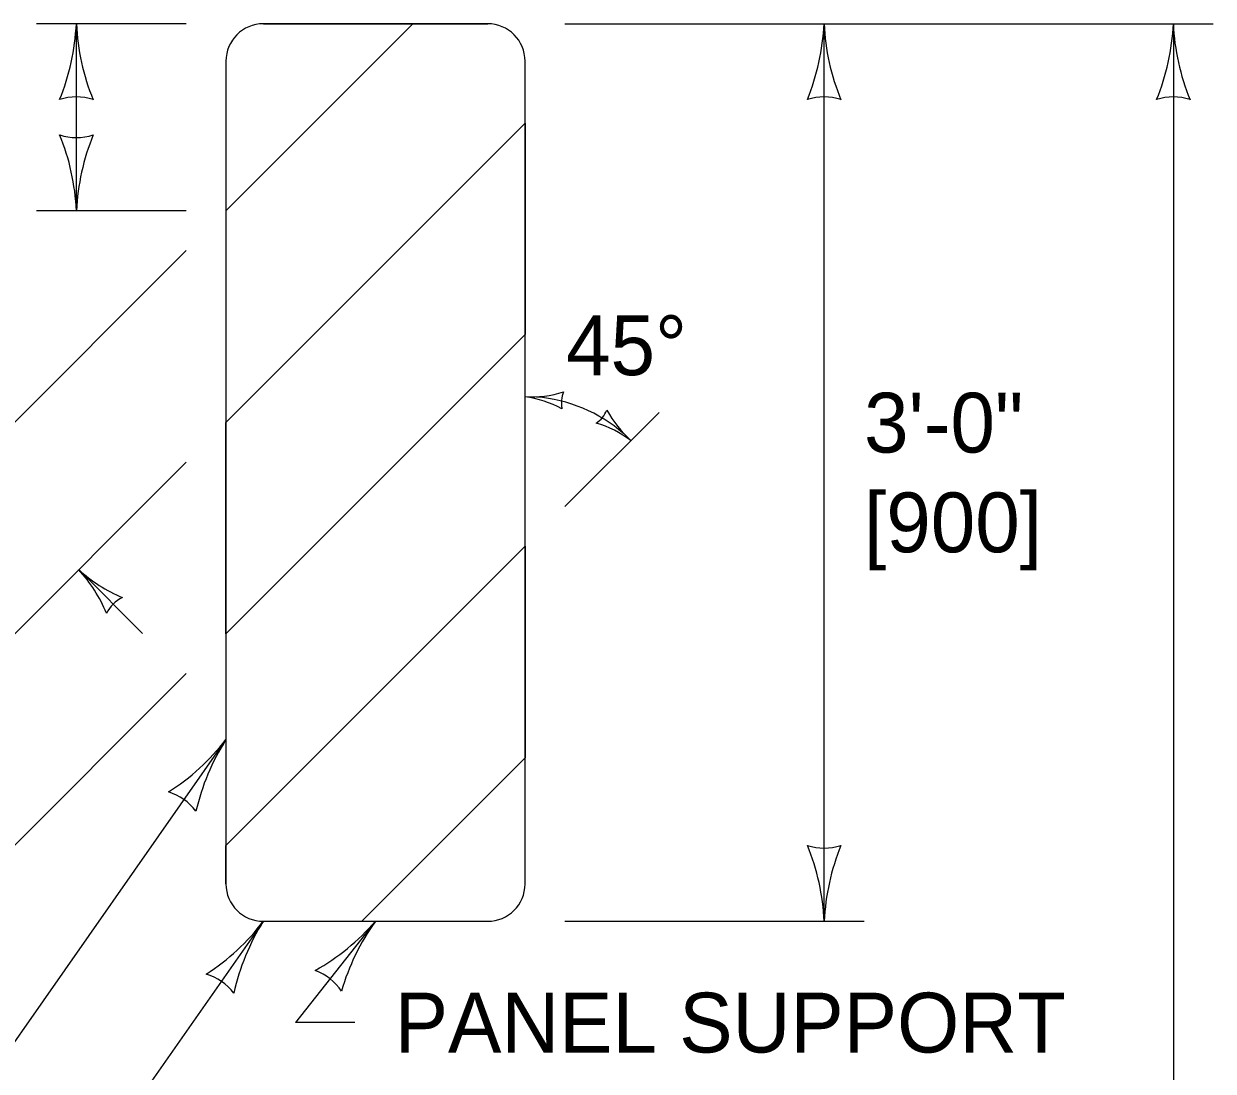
# Model space of a CAD drawing. Extents: x 49991.4 to 50024.6, y 49987.6 to 50011.4.
# Drawn here: x 50012.267 to 50013.46, y 49996.958 to 49998.009 of the extents above; entities that cross this region are included whole.
import ezdxf

# ---------------------------------------------------------------- set-up
doc = ezdxf.new("R2010")
doc.units = 0
doc.layers.add('Level 2', color=7, linetype='Continuous')
doc.layers.add('Level 3', color=7, linetype='Continuous')

msp = doc.modelspace()

# ---------------------------------------------------------------- linework, layer by layer
at = {"layer": 'Level 2'}
for p, q in [((50012.6573, 49998.0086), (50012.4698, 49997.8211)), ((50012.7323, 49998.0086), (50012.6573, 49998.0086)), ((50012.4698, 49997.6089), (50012.7698, 49997.9089)), ((50012.7698, 49997.9089), (50012.7698, 49997.6969)), ((50012.7698, 49997.6969), (50012.4698, 49997.3969)), ((50012.4698, 49997.3969), (50012.4698, 49997.6089)), ((50012.4698, 49997.1847), (50012.7698, 49997.4847)), ((50012.7698, 49997.4847), (50012.7698, 49997.2725)), ((50012.7698, 49997.2725), (50012.6059, 49997.1086)), ((50012.4698, 49997.1461), (50012.4698, 49997.1847))]:
    msp.add_line(p, q, dxfattribs=at)
for points in [[(50012.5073, 49998.0086), (50012.7323, 49998.0086)], [(50012.7323, 49998.0086), (50012.5073, 49998.0086)], [(50012.4698, 49997.9711), (50012.4698, 49997.1461)], [(50012.4698, 49997.9711), (50012.4698, 49997.1461)], [(50012.7698, 49997.1461), (50012.7698, 49997.9711)], [(50012.5073, 49997.1086), (50012.7323, 49997.1086)], [(50012.5073, 49997.1086), (50012.7323, 49997.1086)]]:
    msp.add_lwpolyline(points, dxfattribs=at)
for centre, start, end in [((50012.5073, 49997.9711), 90, 180), ((50012.5073, 49997.9711), 90, 180), ((50012.7323, 49997.9711), 0, 90), ((50012.5073, 49997.1461), 180, 270), ((50012.5073, 49997.1461), 180, 270), ((50012.7323, 49997.1461), 270, 0)]:
    msp.add_arc(centre, 0.0375, start, end, dxfattribs=at)
at = {"layer": 'Level 3'}
for p, q in [((50012.4298, 49998.0086), (50012.2798, 49998.0086)), ((50012.3198, 49997.8211), (50012.3198, 49998.0086)), ((50012.8098, 49998.0086), (50013.46, 49998.0086)), ((50013.0698, 49997.1086), (50013.0698, 49998.0086)), ((50013.42, 49998.0086), (50013.42, 49996.8086)), ((50012.4298, 49997.8211), (50012.2798, 49997.8211)), ((50012.1877, 49997.539), (50012.4298, 49997.7811)), ((50012.8098, 49997.5246), (50012.9043, 49997.6188)), ((50012.0557, 49997.1948), (50012.4298, 49997.5689)), ((50012.3862, 49997.3971), (50012.3221, 49997.4612)), ((50012.4698, 49997.3969), (50012.4698, 49997.1847)), ((50012.1617, 49997.0888), (50012.4298, 49997.3569)), ((50012.4698, 49997.2908), (50011.8076, 49996.3452)), ((50012.5073, 49997.1086), (50012.1656, 49996.6207)), ((50012.6198, 49997.1086), (50012.5394, 49997.007)), ((50012.8098, 49997.1086), (50013.1098, 49997.1086)), ((50012.599, 49997.007), (50012.5394, 49997.007))]:
    msp.add_line(p, q, dxfattribs=at)
for centre, radius, start, end in [((50012.087, 49998.0201), 0.233, 337.9228, 357.1727), ((50012.5419, 49998.0177), 0.2223, 182.3605, 202.544), ((50012.837, 49998.0201), 0.233, 337.9228, 357.1727), ((50013.2919, 49998.0177), 0.2223, 182.3605, 202.544), ((50013.1873, 49998.0201), 0.233, 337.9228, 357.1727), ((50013.6421, 49998.0177), 0.2223, 182.3605, 202.544), ((50012.3198, 49997.8804), 0.0548, 72.1388, 107.8612), ((50013.0698, 49997.8804), 0.0548, 72.1388, 107.8612), ((50013.42, 49997.8804), 0.0548, 72.1388, 107.8612), ((50012.0976, 49997.8119), 0.2223, 2.3605, 22.544), ((50012.3198, 49997.9493), 0.0548, 252.1388, 287.8612), ((50012.5525, 49997.8096), 0.233, 157.9228, 177.1727), ((50012.7759, 49997.7457), 0.1112, 266.8133, 286.9968), ((50012.7528, 49997.5194), 0.1165, 62.3756, 81.6255), ((50012.7698, 49997.4847), 0.15, 48.8596, 85.6704), ((50012.8336, 49997.6285), 0.0274, 156.5916, 192.314), ((50012.8263, 49997.6312), 0.0274, 302.8834, 338.6057), ((50012.9541, 49997.677), 0.1165, 208.6674, 227.9172), ((50012.8092, 49997.5017), 0.1112, 53.105, 73.2885), ((50012.213, 49997.3608), 0.1482, 22.456, 42.6395), ((50012.4263, 49997.5763), 0.1553, 227.8273, 247.0772), ((50012.3825, 49997.4007), 0.0365, 117.1388, 152.8612), ((50012.2934, 49997.4262), 0.2223, 302.2887, 322.4722), ((50012.6666, 49997.1661), 0.233, 147.66, 166.9099), ((50012.3959, 49997.186), 0.0548, 36.9715, 72.6939), ((50012.8476, 49997.0994), 0.2223, 2.3605, 22.544), ((50013.0698, 49997.2368), 0.0548, 252.1388, 287.8612), ((50013.3025, 49997.0971), 0.233, 157.9228, 177.1727), ((50012.33, 49997.2428), 0.2223, 302.672, 322.8555), ((50012.7049, 49996.9853), 0.233, 148.0433, 167.2931), ((50012.4444, 49997.262), 0.233, 299.5774, 318.8272), ((50012.7996, 49996.9779), 0.2223, 144.015, 164.1985), ((50012.5402, 49997.008), 0.0548, 33.7934, 69.5157), ((50012.4341, 49997.0033), 0.0548, 37.3548, 73.0772)]:
    msp.add_arc(centre, radius, start, end, dxfattribs=at)

# ---------------------------------------------------------------- texts
at = {"layer": 'Level 2'}
for s, p in [('45°', (50012.8109, 49997.6562)), ('3\'-0"', (50013.1098, 49997.5786)), ('[900]', (50013.1098, 49997.4786)), ('PANEL SUPPORT', (50012.639, 49996.977))]:
    msp.add_text(s, height=0.06, dxfattribs=at).set_placement(p)

doc.saveas('drawing.dxf')
